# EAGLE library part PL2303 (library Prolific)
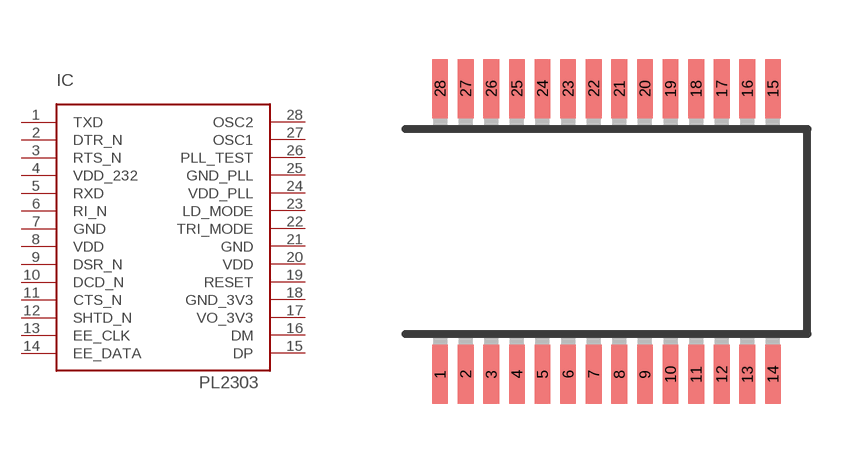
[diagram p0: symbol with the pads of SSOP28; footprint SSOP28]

Designator prefix IC

## PL2303  [SSOP28]
1  TXD  out
2  DTR_N  out
3  RTS_N  out
4  VDD_232  pwr
5  RXD  in
6  RI_N  in
7  GND  pwr
8  VDD  pwr
9  DSR_N  in
10  DCD_N  in
11  CTS_N  in
12  SHTD_N  out
13  EE_CLK
14  EE_DATA
15  DP
16  DM
17  VO_3V3  pwr
18  GND_3V3  pwr
19  RESET  in
20  VDD  pwr
21  GND  pwr
22  TRI_MODE  in
23  LD_MODE
24  VDD_PLL  pwr
25  GND_PLL  pwr
26  PLL_TEST  in
27  OSC1  in
28  OSC2  out

## Footprint SSOP28 (pad centres in mm)
smd 0.4 x 1.5: 1 -4.225,-3.625; 2 -3.575,-3.625; 3 -2.925,-3.625; 4 -2.275,-3.625; 5 -1.625,-3.625; 6 -0.975,-3.625; 7 -0.325,-3.625; 8 0.325,-3.625; 9 0.975,-3.625; 10 1.625,-3.625; 11 2.275,-3.625; 12 2.925,-3.625; 13 3.575,-3.625; 14 4.225,-3.625; 15 4.225,3.625; 16 3.575,3.625; 17 2.925,3.625; 18 2.275,3.625; 19 1.625,3.625; 20 0.975,3.625; 21 0.325,3.625; 22 -0.325,3.625; 23 -0.975,3.625; 24 -1.625,3.625; 25 -2.275,3.625; 26 -2.925,3.625; 27 -3.575,3.625; 28 -4.225,3.625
